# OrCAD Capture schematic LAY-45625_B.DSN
size A4; rev: 00; note: JN518x MEZZANINE
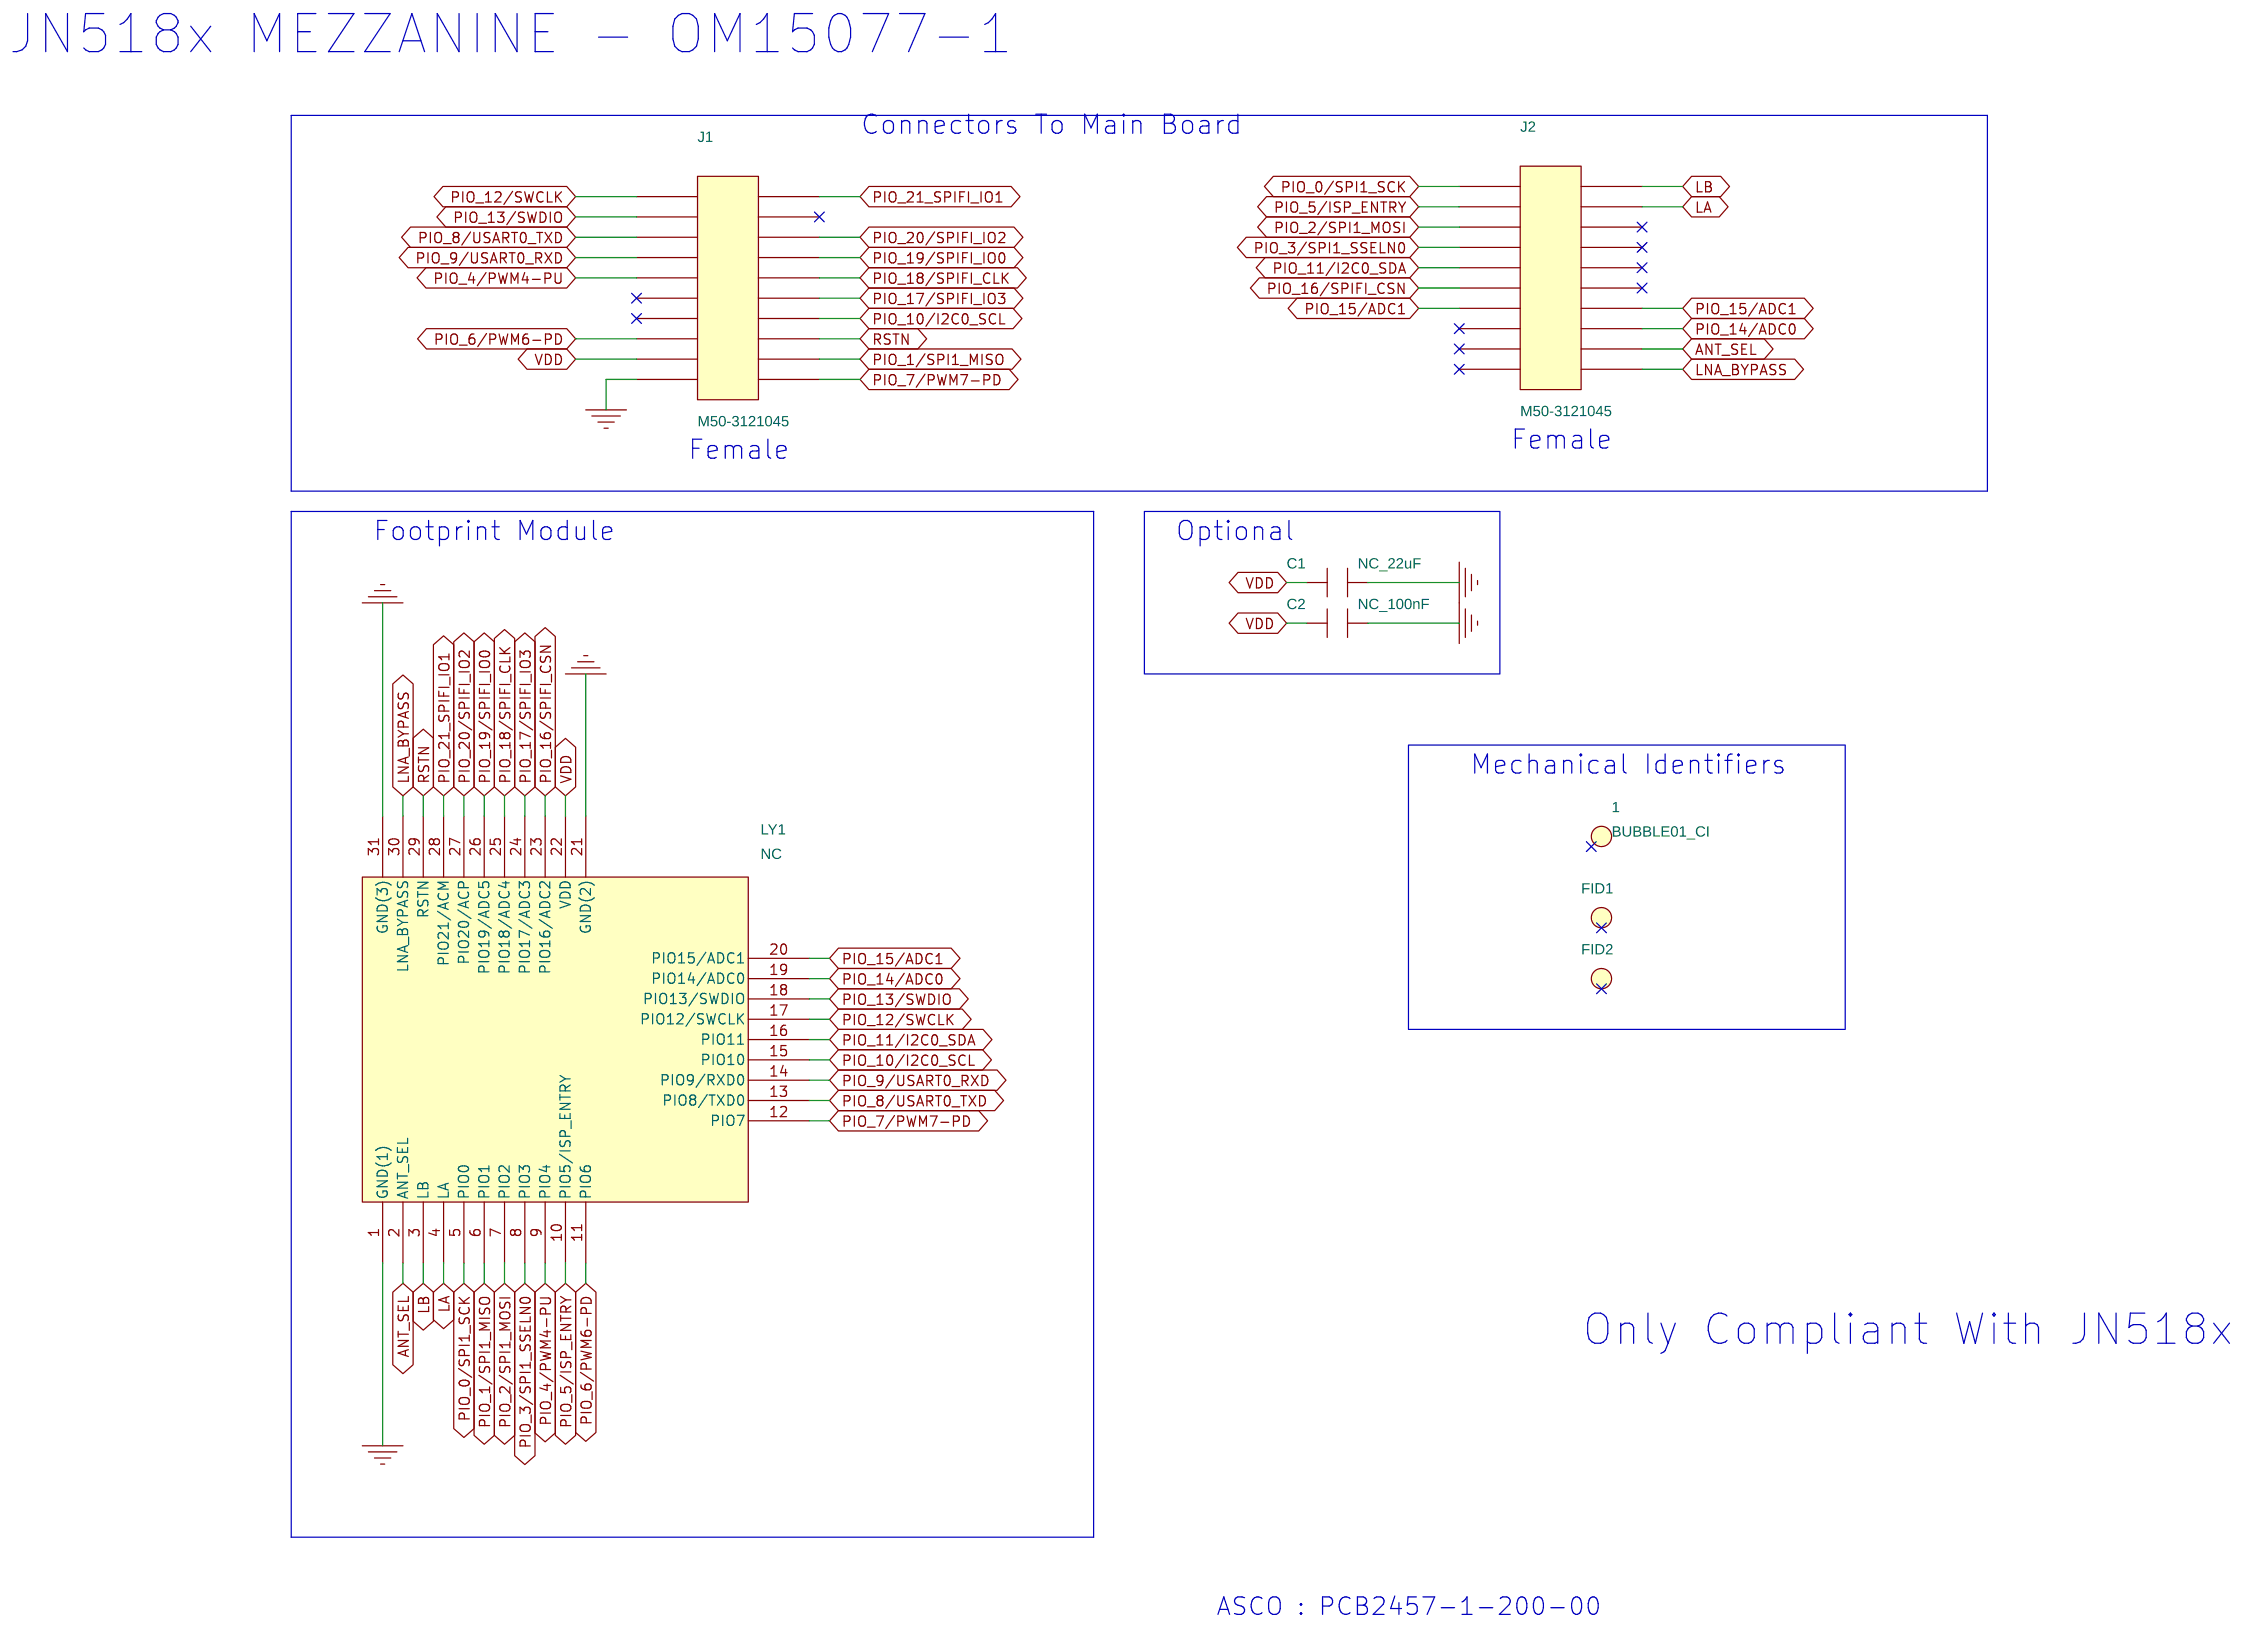
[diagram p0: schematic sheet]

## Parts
1  BUBBLE01_CI  [BUBBLE_DIAM8]
C1  NC_22uF  [C0805]
C2  NC_100nF  [C0402]
FID1  NC  [FID1]
FID2  NC  [FID1]
J1  M50-3121045  [m50-3121045]
J2  M50-3121045  [m50-3121045]
LY1  NC  [smd_lyre_31pts_mezza_jn518x]

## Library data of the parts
1 = BUBBLE: Designation: Printed Circuit Board : OM15077-1 (NXP : Mezzanine board JN518x (HVQFN40)); Manufacturer_reference: PCB2457-1; Part Number: 0-00-0CI_OM15077-1; Part Type: BUBBLE_CI; Supplier: ASCO
C1 = CAPA: Alt_Symbols: 0805C; Designation: !!! NOT CONNECTED !!! Capacitor 0805 22uF 20% 6.3V X7T (-55°C+125°C); Gamme: X7T; MANUFACTURER_REFERENCE: MURATA (GRM21BD70J226ME44); Package: 805; Part Number: NC_0-00-3GRM21-22uF_1; Supplier: DIGIKEY CORPORATION; Temp: (-55°C+125°C); Tension: 6.3V; Tol: 20%
C2 = CAPA: Alt_Symbols: 0402C; Designation: !!! NOT CONNECTED !!! Capacitor 0402 100nF 5% 10V X7R (-55°C+125°C); Gamme: X7R; MANUFACTURER_REFERENCE: MURATA (GRM155R71A104JA01#); Package: 402; Part Number: NC_0-00-3GRM155-100nF_1; Supplier: DIGIKEY CORPORATION; Temp: (-55°C+125°C); Tension: 10V; Tol: 5%
FID1 FID2 = MIRE: Designation: !!! Not Connected !!!; Part Number: 0-00-2MIRE_FID_NC; Part Type: MISC
J1 J2 = CON20AP: Designation: HEADER 2x10 Pts Fem SMT; Manufacturer_reference: HARWIN (M50-3121045), Harwin Inc (M50-3121045); Package: HEADER; Part Number: 0-00-202944; Part Type: CONNECTOR
LY1 = LYRE_MODJN518x_31PTS: Designation: !!! Not Connected !!!; Manufacturer_reference: NXP; Package: LYRE; Part Number: 0-00-2LYREMEZJN518x_31_NC; Part Type: LYRE

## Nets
GND: C1.2 C2.2 J1.19 LY1.1(GND(1)) LY1.21(GND(2)) LY1.31(GND(3))
VDD: C1.1 C2.1 J1.17 LY1.22(VDD)
ANT_SEL: J2.18 LY1.2(ANT_SEL)
LA: J2.4 LY1.4(LA)
LB: J2.2 LY1.3(LB)
LNA_BYPASS: J2.20 LY1.30(LNA_BYPASS)
PIO_0/SPI1_SCK: J2.1 LY1.5(PIO0)
PIO_1/SPI1_MISO: J1.18 LY1.6(PIO1)
PIO_2/SPI1_MOSI: J2.5 LY1.7(PIO2)
PIO_3/SPI1_SSELN0: J2.7 LY1.8(PIO3)
PIO_4/PWM4-PU: J1.9 LY1.9(PIO4)
PIO_5/ISP_ENTRY: J2.3 LY1.10(PIO5/ISP_ENTRY)
PIO_6/PWM6-PD: J1.15 LY1.11(PIO6)
PIO_7/PWM7-PD: J1.20 LY1.12(PIO7)
PIO_8/USART0_TXD: J1.5 LY1.13(PIO8/TXD0)
PIO_9/USART0_RXD: J1.7 LY1.14(PIO9/RXD0)
PIO_10/I2C0_SCL: J1.14 LY1.15(PIO10)
PIO_11/I2C0_SDA: J2.9 LY1.16(PIO11)
PIO_12/SWCLK: J1.1 LY1.17(PIO12/SWCLK)
PIO_13/SWDIO: J1.3 LY1.18(PIO13/SWDIO)
PIO_14/ADC0: J2.16 LY1.19(PIO14/ADC0)
PIO_15/ADC1: J2.13 J2.14 LY1.20(PIO15/ADC1)
PIO_16/SPIFI_CSN: J2.11 LY1.23(PIO16/ADC2)
PIO_17/SPIFI_IO3: J1.12 LY1.24(PIO17/ADC3)
PIO_18/SPIFI_CLK: J1.10 LY1.25(PIO18/ADC4)
PIO_19/SPIFI_IO0: J1.8 LY1.26(PIO19/ADC5)
PIO_20/SPIFI_IO2: J1.6 LY1.27(PIO20/ACP)
PIO_21_SPIFI_IO1: J1.2 LY1.28(PIO21/ACM)
RSTN: J1.16 LY1.29(RSTN)

Not connected (* = marked no-connect by the designer): 1 1*; FID1 1*; FID2 1*; J1 4* 11* 13*; J2 6* 8* 10* 12* 15* 17* 19*

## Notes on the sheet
- JN518x MEZZANINE - OM15077-1
- Connectors To Main Board
- Female
- Female
- Footprint Module
- Optional
- Mechanical Identifiers
- Only Compliant With JN518x
- ASCO : PCB2457-1-200-00
